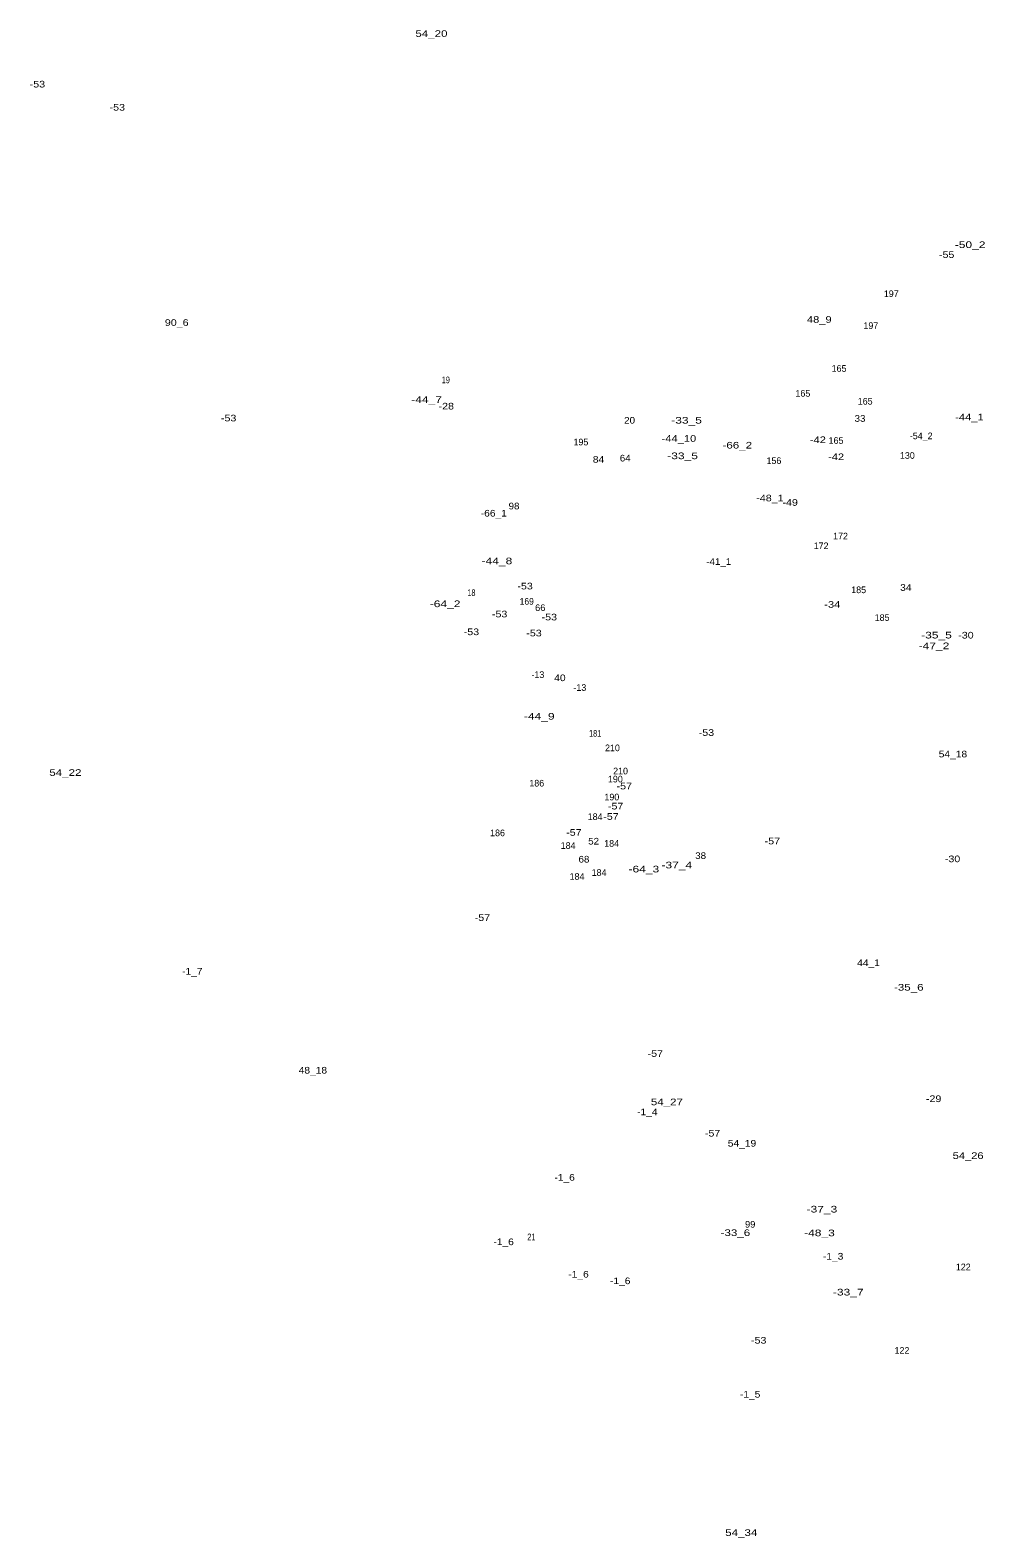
# Model space of a CAD drawing. Extents: x -660405 to -657848, y -988475 to -986360.
# Drawn here: x -659548 to -658974, y -988210 to -987303 of the extents above; entities that cross this region are included whole.
import ezdxf
from ezdxf.enums import TextEntityAlignment as Align

# ---------------------------------------------------------------- set-up
doc = ezdxf.new("R2010")
doc.units = 0
doc.header["$LTSCALE"] = 1.6
doc.layers.add('24', color=7, linetype='Continuous')

msp = doc.modelspace()

# ---------------------------------------------------------------- texts
at = {"layer": '24'}
for s, width, p in [('54_20', 1.3, (-659306.52, -987306.57)), ('-53', 1.2, (-659543.62, -987337)), ('-53', 1.2, (-659495.54, -987350.92)), ('-50_2', 1.35, (-658982.38, -987433.58)), ('-55', 1.2, (-658996.49, -987439.55)), ('48_9', 1.25, (-659073.13, -987478.57)), ('90_6', 1.2, (-659459.78, -987480.42)), ('19', 0.8, (-659297.861, -987514.91)), ('-44_7', 1.35, (-659309.4, -987526.73)), ('-28', 1.2, (-659297.58, -987530.72)), ('-53', 1.2, (-659428.53, -987537.88)), ('20', 1.1, (-659187.28, -987539.2)), ('-33_5', 1.35, (-659153, -987539.21)), ('33', 1.1, (-659048.63, -987538.11)), ('-44_1', 1.25, (-658982.8, -987537.31)), ('-44_10', 1.25, (-659157.6, -987550.15)), ('-42', 1.25, (-659073.99, -987550.95)), ('64', 1.1, (-659189.9, -987561.98)), ('-33_5', 1.35, (-659155.38, -987560.6)), ('-66_2', 1.3, (-659122.47, -987554.21)), ('-42', 1.25, (-659063.03, -987561.19)), ('84', 1.15, (-659205.98, -987562.72)), ('-48_1', 1.2, (-659102.84, -987585.98)), ('-49', 1.2, (-659090.66, -987588.64)), ('-66_1', 1.15, (-659268.96, -987595.12)), ('98', 1.1, (-659256.82, -987590.79)), ('-44_8', 1.35, (-659267.1, -987623.83)), ('-41_1', 1.1, (-659133.65, -987624.18)), ('18', 0.8, (-659282.459, -987642.94)), ('-53', 1.2, (-659250.15, -987638.97)), ('34', 1.15, (-659021.059, -987639.8)), ('-64_2', 1.35, (-659298.3, -987649.62)), ('169', 0.95, (-659249.17, -987648.16)), ('66', 1.05, (-659241.02, -987651.97)), ('-34', 1.25, (-659065.31, -987649.99)), ('-53', 1.2, (-659265.47, -987655.77)), ('-53', 1.2, (-659235.58, -987657.61)), ('-53', 1.2, (-659282.44, -987666.47)), ('-53', 1.2, (-659244.8, -987667.21)), ('-35_5', 1.35, (-659002.61, -987668.47)), ('-30', 1.2, (-658984.9, -987668.5)), ('-47_2', 1.35, (-659004.1, -987674.91)), ('40', 1.15, (-659229.199, -987694.14)), ('-44_9', 1.35, (-659241.64, -987717.3)), ('181', 0.8, (-659208, -987727.56)), ('-53', 1.2, (-659141.05, -987727.06)), ('54_18', 1.15, (-658992.72, -987740)), ('54_22', 1.3, (-659526.77, -987751.13)), ('-57', 1.2, (-659190.481, -987759.28)), ('-57', 1.2, (-659198.481, -987777.56)), ('-57', 1.2, (-659195.671, -987771.33)), ('-57', 1.2, (-659220.811, -987787.16)), ('52', 1.1, (-659208.919, -987792.43)), ('-57', 1.2, (-659101.38, -987792.35)), ('68', 1.1, (-659214.73, -987803.27)), ('-37_4', 1.35, (-659158.87, -987806.79)), ('38', 1.1, (-659144.52, -987801.13)), ('-30', 1.2, (-658992.94, -987803.06)), ('-64_3', 1.35, (-659178.69, -987809.22)), ('-57', 1.2, (-659275.831, -987838.37)), ('44_1', 1.15, (-659043.49, -987865.56)), ('-1_7', 1.15, (-659450.41, -987870.69)), ('-35_6', 1.3, (-659019.29, -987880.3)), ('-57', 1.2, (-659171.821, -987920.17)), ('48_18', 1.15, (-659377.85, -987930.22)), ('54_27', 1.3, (-659164.84, -987949.27)), ('-29', 1.2, (-659004.32, -987947.37)), ('-1_4', 1.15, (-659176.6, -987955.25)), ('-57', 1.2, (-659137.321, -987968.12)), ('54_19', 1.15, (-659119.64, -987974.16)), ('54_26', 1.25, (-658983.569, -987981.58)), ('-1_6', 1.15, (-659226.37, -987994.69)), ('-37_3', 1.35, (-659071.54, -988013.8)), ('99', 1.05, (-659114.7, -988022.92)), ('-1_6', 1.15, (-659263.081, -988033.44)), ('21', 0.8, (-659246.35, -988030.48)), ('-33_6', 1.3, (-659123.61, -988027.95)), ('-48_3', 1.35, (-659073.04, -988028.08)), ('-1_3', 1.15, (-659064.799, -988042.12)), ('-1_6', 1.15, (-659218.02, -988052.94)), ('-1_6', 1.15, (-659192.931, -988056.91)), ('-33_7', 1.35, (-659055.69, -988063.72)), ('-53', 1.2, (-659109.59, -988092.68)), ('-1_5', 1.15, (-659114.74, -988125.16)), ('54_34', 1.3, (-659120.071, -988208.37))]:
    msp.add_text(s, height=4, dxfattribs=dict(at, width=width)).set_placement(p, align=Align.CENTER)
for s, p in [('197', (-659029.83, -987463.07)), ('197', (-659042.1, -987482.26)), ('165', (-659061.24, -987508.03)), ('165', (-659083, -987523.03)), ('165', (-659045.52, -987527.78)), ('195', (-659216.561, -987552.3)), ('165', (-659063.071, -987551.37)), ('-54_2', (-659011.807, -987548.59)), ('130', (-659020.14, -987560.38)), ('156', (-659100.421, -987563.52)), ('172', (-659072.051, -987614.73)), ('172', (-659060.351, -987608.87)), ('185', (-659049.449, -987641.2)), ('185', (-659035.34, -987657.9)), ('-13', (-659242.471, -987692.22)), ('-13', (-659217.201, -987699.97)), ('210', (-659197.6, -987736.28)), ('210', (-659192.71, -987750.22)), ('186', (-659243.13, -987757.52)), ('190', (-659195.831, -987755.07)), ('190', (-659197.951, -987765.86)), ('184', (-659208.03, -987777.69)), ('186', (-659266.75, -987787.42)), ('184', (-659224.26, -987795.03)), ('184', (-659198.069, -987793.74)), ('184', (-659218.91, -987813.67)), ('184', (-659205.63, -987811.27)), ('122', (-658986.48, -988048.53)), ('122', (-659023.4, -988098.78))]:
    msp.add_text(s, height=4, dxfattribs=at).set_placement(p, align=Align.CENTER)

doc.saveas('drawing.dxf')
